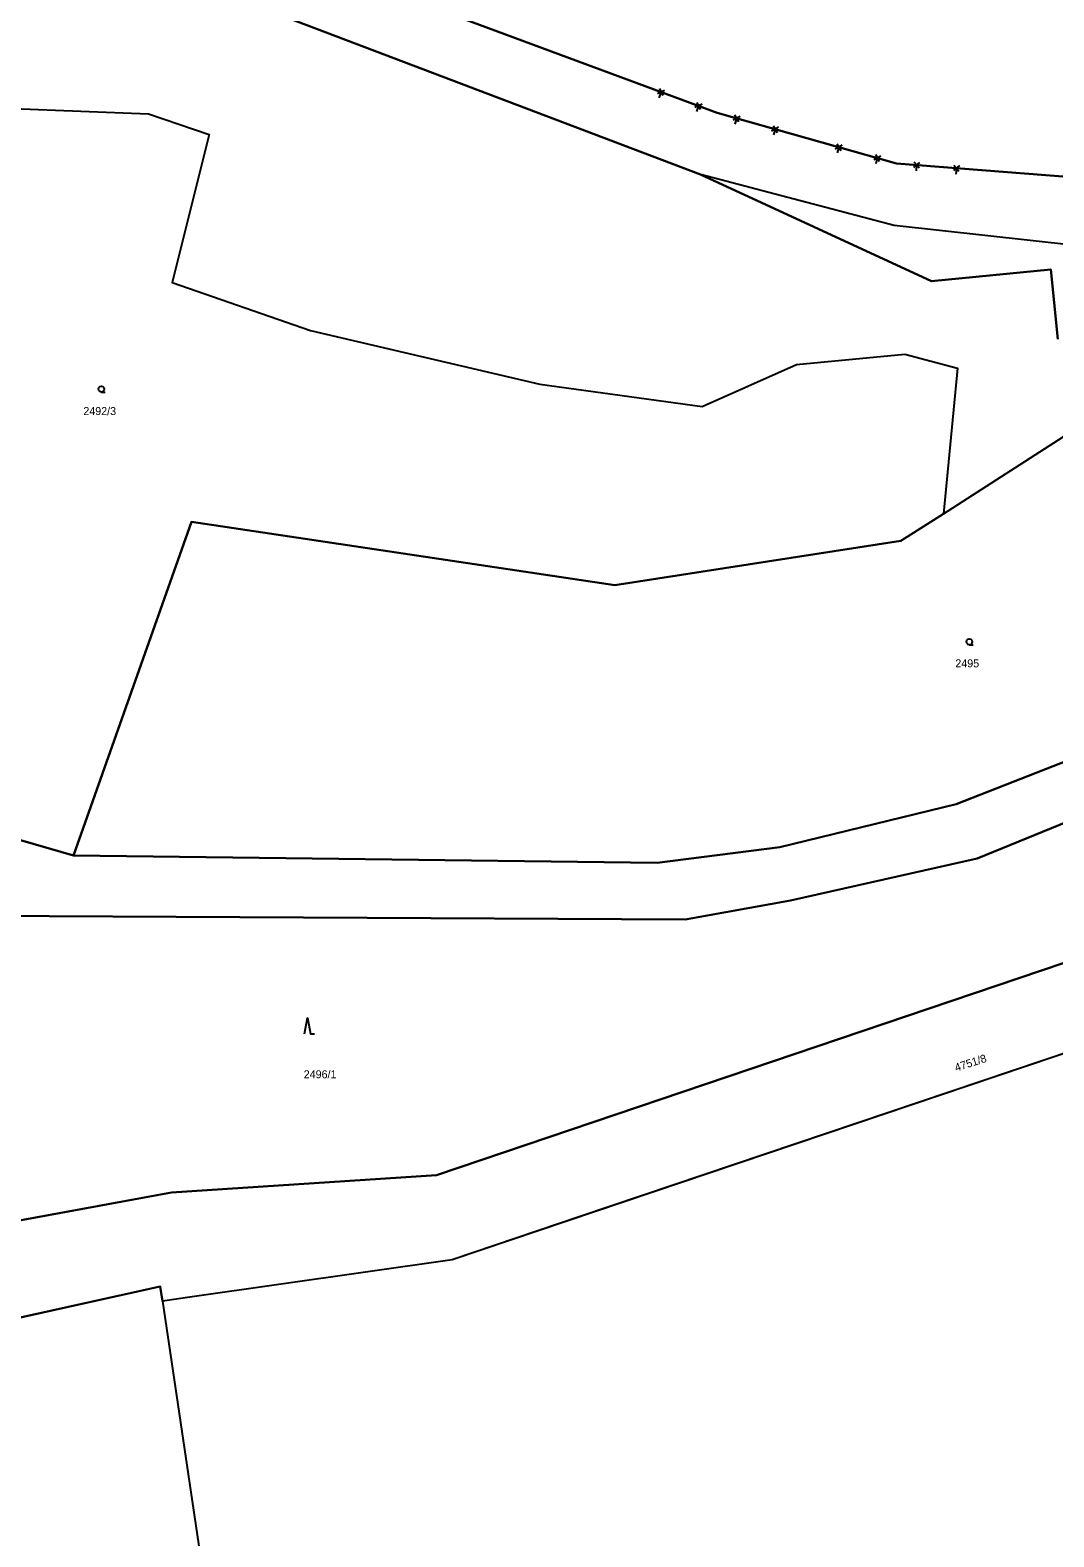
# Model space of a CAD drawing. Extents: x -439750 to -439180, y -1258684 to -1258308.
# Drawn here: x -439362.4 to -439311.2, y -1258429.7 to -1258354.4 of the extents above; entities that cross this region are included whole.
import ezdxf

# ---------------------------------------------------------------- set-up
doc = ezdxf.new("R2010")
doc.units = 0
doc.layers.add('KATASTER', color=7, linetype='Continuous')
doc.layers.add('UOV', color=7, linetype='Continuous')

# ---------------------------------------------------------------- blocks, each defined once
blk = doc.blocks.new('304')
blk.add_lwpolyline([(0, 0), (-0.38, 0.1), (-0.65, 0.37), (-0.75, 0.74), (-0.65, 1.11), (-0.38, 1.38), (-0.01, 1.48), (0.36, 1.38), (0.63, 1.11), (0.73, 0.73), (0.63, 0.35), (0.36, 0.08), (-0.02, -0.02), (0.98, -0.02)])
blk = doc.blocks.new('308')
blk.add_lwpolyline([(-0.75, 0), (0, 4), (0.75, 0), (1.75, 0)])
blk = doc.blocks.new('2072')
for p, q in [((-4.3, 0.7), (-5.7, -0.7)), ((-5.7, 0.7), (-4.3, -0.7)), ((-5, 0), (-5, -1.5)), ((4.3, 0.7), (5.7, -0.7)), ((5.7, 0.7), (4.3, -0.7)), ((5, 0), (5, -1.5))]:
    blk.add_line(p, q)

msp = doc.modelspace()

# ---------------------------------------------------------------- linework, layer by layer
at = {"layer": 'KATASTER'}
for points in [[(-439255.265, -1258349.384), (-439254.59, -1258356.61), (-439259.45, -1258374.06), (-439265.25, -1258367.53), (-439273.81, -1258367.89), (-439294.34, -1258362.99), (-439319.08, -1258361.05), (-439328.04, -1258358.53), (-439357.98, -1258347.42), (-439361.22, -1258351.62), (-439365.48, -1258348.34), (-439391.19, -1258328.53), (-439415.15, -1258317.05), (-439445.45, -1258309.53), (-439455.48, -1258307.79), (-439478.63, -1258311.39), (-439488.88, -1258312.99), (-439507.94, -1258320.79), (-439517.56, -1258326.72), (-439510.66, -1258363.93), (-439529.05, -1258372.98), (-439583.01, -1258405.44)], [(-439583.01, -1258405.44), (-439529.05, -1258372.98), (-439510.66, -1258363.93), (-439517.56, -1258326.72), (-439507.94, -1258320.79), (-439488.88, -1258312.99), (-439478.63, -1258311.39), (-439455.48, -1258307.79), (-439445.45, -1258309.53), (-439415.15, -1258317.05), (-439391.19, -1258328.53), (-439365.48, -1258348.34), (-439361.22, -1258351.62), (-439357.98, -1258347.42), (-439328.04, -1258358.53), (-439319.08, -1258361.05), (-439294.34, -1258362.99), (-439273.81, -1258367.89), (-439265.25, -1258367.53), (-439259.45, -1258374.06), (-439254.59, -1258356.61), (-439255.265, -1258349.384)], [(-439583.01, -1258405.44), (-439529.05, -1258372.98), (-439510.66, -1258363.93), (-439469.66, -1258359.58), (-439457.56, -1258358.3), (-439442.28, -1258360.05), (-439426.53, -1258366.38), (-439414.38, -1258373.64), (-439402.31, -1258380.87), (-439389.09, -1258387.3), (-439380.93, -1258392.19), (-439379.33, -1258392.51), (-439372.39, -1258393.61), (-439364.9, -1258394.3), (-439360.22, -1258395.64), (-439331.05, -1258396.01), (-439324.92, -1258395.23), (-439316.1, -1258393.08), (-439301.55, -1258387.38)], [(-439269.36, -1258377.15), (-439315.05, -1258395.8), (-439324.38, -1258397.9), (-439329.65, -1258398.85), (-439367.83, -1258398.64), (-439381.39, -1258394.16), (-439403.76, -1258383.09), (-439428.41, -1258368.76), (-439442.76, -1258364.07), (-439458.37, -1258362.23), (-439513.27, -1258367.25), (-439515.07, -1258371.54), (-439519.61, -1258372.16), (-439523.86, -1258373.74), (-439527.84, -1258376.06), (-439569.67, -1258401.31)], [(-439547.65, -1258418.05), (-439537.73, -1258410.35), (-439527.28, -1258405.47), (-439520.18, -1258404.63), (-439512.57, -1258405.64), (-439506.61, -1258407.45), (-439484.43, -1258417.81), (-439474.81, -1258422.32), (-439466.86, -1258425.16), (-439456.86, -1258427.2), (-439444.81, -1258427.42), (-439422.62, -1258423.93), (-439418.29, -1258423.4), (-439390.34, -1258418.93), (-439355.32, -1258412.49), (-439342.07, -1258411.63), (-439307.35, -1258399.88)], [(-439304.03, -1258403.29), (-439334.89, -1258413.69), (-439341.3, -1258415.85), (-439354.3, -1258417.7), (-439355.78, -1258417.92), (-439355.89, -1258417.18), (-439387.21, -1258424.13), (-439387, -1258423.44), (-439415.05, -1258427.42), (-439434.74, -1258431.72), (-439442.45, -1258432.5), (-439453.89, -1258431.74), (-439461.05, -1258431.03), (-439498.8, -1258414.92), (-439505.79, -1258411.63), (-439510.78, -1258409.92), (-439521.49, -1258405.8), (-439531.73, -1258411.37), (-439536.05, -1258413.64), (-439546.05, -1258421.31)], [(-439342.84, -1258481.76), (-439376.6, -1258488.12), (-439398.93, -1258492.76), (-439393.11, -1258458.67), (-439387.21, -1258424.13), (-439355.89, -1258417.18), (-439355.78, -1258417.92), (-439352.04, -1258443.07), (-439355.61, -1258442.12), (-439357.86, -1258441.52), (-439357.71, -1258440.96), (-439364.32, -1258439.2), (-439364.24, -1258438.91), (-439373.38, -1258436.31), (-439372.9, -1258433.44), (-439378.54, -1258432.5), (-439378.83, -1258437.55), (-439380.62, -1258447.31), (-439375.42, -1258449.5)]]:
    msp.add_lwpolyline(points, dxfattribs=at)
for points in [[(-439267.42, -1258373.23), (-439276.35, -1258376.67), (-439276.71, -1258375.89), (-439277.2, -1258372.87), (-439277.72, -1258370.76), (-439296.68, -1258366.63), (-439319.2, -1258364.15), (-439328.88, -1258361.61), (-439351.95, -1258352.84), (-439361.22, -1258351.62), (-439357.98, -1258347.42), (-439328.04, -1258358.53), (-439319.08, -1258361.05), (-439294.34, -1258362.99), (-439273.81, -1258367.89), (-439265.25, -1258367.53)], [(-439366.64, -1258358.17), (-439356.47, -1258358.58), (-439353.45, -1258359.6), (-439355.3, -1258367), (-439348.37, -1258369.41), (-439336.92, -1258372.08), (-439328.8, -1258373.21), (-439324.08, -1258371.11), (-439318.67, -1258370.58), (-439316.03, -1258371.29), (-439316.73, -1258378.56), (-439318.87, -1258379.92), (-439333.16, -1258382.13), (-439354.32, -1258378.96), (-439360.22, -1258395.64), (-439364.9, -1258394.3), (-439369.09, -1258392.03), (-439364.8, -1258384.93), (-439365.06, -1258384.77), (-439363.43, -1258382.08), (-439371.73, -1258377.06), (-439372.95, -1258379.77), (-439379.94, -1258375.52), (-439385.11, -1258380.51)], [(-439360.22, -1258395.64), (-439354.32, -1258378.96), (-439333.16, -1258382.13), (-439318.87, -1258379.92), (-439316.73, -1258378.56), (-439308.31, -1258373.15), (-439277.72, -1258370.76), (-439277.2, -1258372.87), (-439283.2, -1258373.92), (-439282.68, -1258376.92), (-439276.71, -1258375.89), (-439276.35, -1258376.67), (-439301.55, -1258387.38), (-439316.1, -1258393.08), (-439324.92, -1258395.23), (-439331.05, -1258396.01)], [(-439269.36, -1258377.15), (-439273.57, -1258384.75), (-439276.5, -1258386.89), (-439278.27, -1258383.72), (-439283.57, -1258386.62), (-439281.42, -1258390.47), (-439287.8, -1258395.11), (-439307.35, -1258399.88), (-439342.07, -1258411.63), (-439355.32, -1258412.49), (-439390.34, -1258418.93), (-439368.16, -1258411.35), (-439367.83, -1258398.64), (-439329.65, -1258398.85), (-439324.38, -1258397.9), (-439315.05, -1258395.8)]]:
    msp.add_lwpolyline(points, close=True, dxfattribs=at)
at = {"layer": 'UOV'}
for points in [[(-439311.02, -1258369.84), (-439311.36, -1258366.36), (-439317.33, -1258366.94), (-439328.88, -1258361.61), (-439351.95, -1258352.84), (-439361.22, -1258351.62), (-439357.98, -1258347.42), (-439328.04, -1258358.53), (-439319.08, -1258361.05), (-439294.34, -1258362.99)], [(-439294.34, -1258362.99), (-439319.08, -1258361.05), (-439328.04, -1258358.53), (-439357.98, -1258347.42), (-439361.22, -1258351.62), (-439351.95, -1258352.84), (-439328.88, -1258361.61), (-439317.33, -1258366.94), (-439311.36, -1258366.36), (-439311.02, -1258369.84)], [(-439301.55, -1258387.38), (-439316.1, -1258393.08), (-439324.92, -1258395.23), (-439331.05, -1258396.01), (-439360.22, -1258395.64), (-439364.9, -1258394.3), (-439367.7, -1258394.04), (-439372.39, -1258393.61), (-439378.2, -1258389.67), (-439379.33, -1258392.51), (-439380.93, -1258392.19), (-439389.09, -1258387.3), (-439402.31, -1258380.87), (-439414.38, -1258373.64), (-439426.53, -1258366.38), (-439442.28, -1258360.05), (-439457.56, -1258358.3), (-439510.66, -1258363.93), (-439529.05, -1258372.98), (-439583.01, -1258405.44)], [(-439307.35, -1258399.88), (-439342.07, -1258411.63), (-439355.32, -1258412.49), (-439368.12, -1258414.84), (-439368.16, -1258411.35), (-439367.83, -1258398.64), (-439367.7, -1258394.04), (-439364.9, -1258394.3), (-439360.22, -1258395.64), (-439331.05, -1258396.01), (-439324.92, -1258395.23), (-439316.1, -1258393.08), (-439301.55, -1258387.38)]]:
    msp.add_lwpolyline(points, dxfattribs=at)
msp.add_lwpolyline([(-439304.03, -1258403.29), (-439341.3, -1258415.85), (-439354.3, -1258417.7), (-439355.78, -1258417.92), (-439355.89, -1258417.18), (-439368.25, -1258419.92), (-439368.12, -1258414.84), (-439355.32, -1258412.49), (-439342.07, -1258411.63), (-439307.35, -1258399.88), (-439287.8, -1258395.11), (-439279.12, -1258394.03), (-439277.15, -1258393.78), (-439252.22, -1258388.27), (-439241.48, -1258387.75), (-439250.33, -1258391.52), (-439274.68, -1258396.43)], close=True, dxfattribs=at)

# ---------------------------------------------------------------- block references
at = {"layer": 'KATASTER', "xscale": 0.2}
for p, yscale, rotation in [((-439329.915, -1258357.834), 0.20000000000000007, -20.350618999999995), ((-439326.115, -1258359.071), 0.19999999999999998, -15.709661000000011), ((-439321.005, -1258360.509), 0.19999999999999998, -15.709661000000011), ((-439317.086, -1258361.206), 0.19999999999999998, -4.479688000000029)]:
    msp.add_blockref('2072', p, dxfattribs=dict(at, yscale=yscale, rotation=rotation))
at = {"layer": 'KATASTER', "xscale": 0.2, "yscale": 0.20000000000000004}
for name, p in [('304', (-439358.83, -1258372.48)), ('304', (-439315.44, -1258385.11)), ('308', (-439348.53, -1258404.55))]:
    msp.add_blockref(name, p, dxfattribs=at)

# ---------------------------------------------------------------- texts
at = {"layer": 'KATASTER'}
for s, p in [('2492/3', (-439359.732, -1258373.63)), ('2495', (-439316.142, -1258386.24)), ('2496/1', (-439348.715, -1258406.78))]:
    msp.add_text(s, height=0.4, dxfattribs=at).set_placement(p)
at = {"layer": 'UOV'}
msp.add_text('4751/8', height=0.4, rotation=18.048, dxfattribs=at).set_placement((-439316.097, -1258406.453))

doc.saveas('drawing.dxf')
